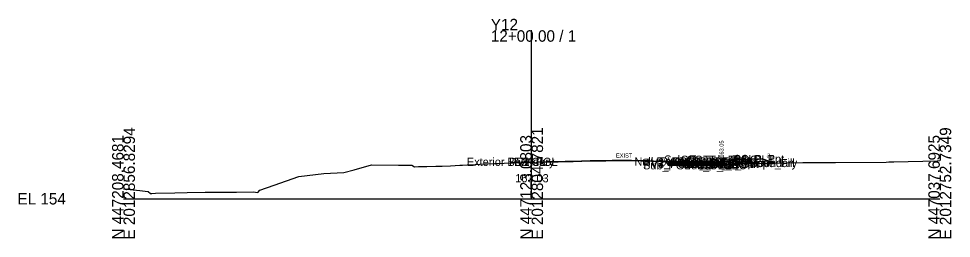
# Model space of a CAD drawing. Extents: x -26 to 1203, y -10 to 9542.
# Drawn here: x -25.7 to 202.8, y 3990.3 to 4044.1 of the extents above; entities that cross this region are included whole.
import ezdxf

# ---------------------------------------------------------------- set-up
doc = ezdxf.new("R2010")
doc.units = 0
for name, color, linetype in [('Default', 7, 'Continuous'), ('Exist Cross Section Cell', 7, 'Continuous'), ('Exist XS Center Line Elevation Label', 7, 'Continuous'), ('Exist XS Ground Line', 7, 'Continuous'), ('Prop CMT Conc Surface', 7, 'Continuous'), ('Prop CMT Concrete Structures', 7, 'Continuous'), ('Prop CMT Pvmt Course 1', 7, 'Continuous'), ('Prop CMT Pvmt Course 1 CG', 7, 'Continuous'), ('Prop CMT Pvmt Course 2', 7, 'Continuous'), ('Prop CMT Pvmt Course 3', 7, 'Continuous'), ('Prop CMT Pvmt Surface', 7, 'Continuous'), ('Prop CMT Slope Grass', 7, 'Continuous'), ('Prop CMT Subgrade Earthwork', 7, 'Continuous'), ('Prop XS Earthwork Shape', 7, 'Continuous'), ('Prop XS Hydro Elevations', 7, 'Continuous'), ('Prop XS SE Text', 7, 'Continuous'), ('Prop XS Side Slope Text', 7, 'Continuous'), ('Scratch_Level_0', 7, 'Continuous')]:
    doc.layers.add(name, color=color, linetype=linetype)

msp = doc.modelspace()

# ---------------------------------------------------------------- linework, layer by layer
at = {"layer": 'Exist Cross Section Cell'}
for p, q in [((100, 4000), (100, 4041.25)), ((0, 4000), (100, 4000)), ((100, 4000), (200, 4000))]:
    msp.add_line(p, q, dxfattribs=at)
at = {"layer": 'Exist XS Ground Line'}
msp.add_lwpolyline([(0, 4002.46), (3.98, 4002), (5.32, 4001.82), (6.04, 4001.75), (6.62, 4001.26), (6.95, 4001.29), (7.8, 4001.38), (12.55, 4001.47), (15.61, 4001.54), (20.02, 4001.61), (27.65, 4001.63), (31.86, 4001.66), (32.36, 4001.62), (32.92, 4001.57), (33.44, 4002.07), (36.88, 4003.29), (42.93, 4005.45), (49.12, 4006.16), (53.97, 4006.45), (56.51, 4007.1), (60.78, 4008.34), (67.35, 4008.23), (70.65, 4008.25), (71.32, 4007.83), (72.27, 4007.86), (73.24, 4007.89), (73.76, 4007.91), (74.31, 4007.9), (76.51, 4007.94), (77.13, 4007.94), (77.71, 4007.95), (78.07, 4007.95), (80.13, 4008.06), (81.29, 4008.13), (82.38, 4008.19), (83.05, 4008.23), (84.22, 4008.29), (86.13, 4008.39), (88.42, 4008.51), (89.05, 4008.53), (90.88, 4008.61), (91.46, 4008.64), (91.81, 4008.65), (93.26, 4008.71), (94.73, 4008.77), (95.66, 4008.82), (97.58, 4008.91), (98.36, 4008.94), (98.9, 4008.71), (99.5, 4009.01), (100, 4009.03), (100.4, 4009.04), (101, 4008.74), (101.38, 4008.98), (103.54, 4009.01), (104.22, 4009.02), (105.33, 4009.05), (106.04, 4009.06), (106.47, 4009.07), (108.25, 4009.11), (109.4, 4009.13), (110.14, 4009.15), (112.34, 4009.2), (114.35, 4009.25), (114.93, 4009.26), (115.25, 4009.27), (115.74, 4009.27), (118.16, 4009.31), (119.71, 4009.34), (121.08, 4009.36), (121.56, 4009.36), (123.21, 4009.36), (124.01, 4009.35), (124.51, 4009.34), (126.94, 4009.29), (127.84, 4009.27), (129.33, 4009.22), (129.89, 4009.2), (131.49, 4009.16), (132.8, 4009.12), (133.49, 4009.1), (135.27, 4009.04), (135.66, 4009.09), (137.45, 4008.92), (141.7, 4008.69), (142.97, 4008.63), (145.36, 4008.52), (147.63, 4008.57), (149.64, 4008.58), (158.4, 4008.74), (166.49, 4008.84), (174.42, 4008.87), (186.85, 4008.99), (187.51, 4009), (188.73, 4009.01), (199.36, 4009.32), (200, 4009.37)], dxfattribs=at)
at = {"layer": 'Prop CMT Conc Surface'}
msp.add_lwpolyline([(144.52, 4009.13), (146.52, 4009.05), (146.52, 4009.55), (147.02, 4009.55)], dxfattribs=at)
at = {"layer": 'Prop CMT Concrete Structures'}
for points in [[(144.52, 4009.13), (146.52, 4009.05), (146.52, 4009.55), (147.02, 4009.55)], [(147.02, 4009.55), (147.02, 4008.55), (144.52, 4008.55)], [(144.52, 4008.55), (144.52, 4009.13)]]:
    msp.add_lwpolyline(points, dxfattribs=at)
at = {"layer": 'Prop CMT Pvmt Course 1'}
for points in [[(133.49, 4009.1), (133.46, 4009.11), (133.28, 4009.11), (132.8, 4009.12), (131.49, 4009.16), (129.89, 4009.2), (129.68, 4009.21), (129.33, 4009.22), (127.84, 4009.27), (126.94, 4009.29), (124.51, 4009.34), (124.01, 4009.35), (123.21, 4009.36), (121.56, 4009.36), (121.08, 4009.36), (119.71, 4009.34), (118.16, 4009.31), (115.74, 4009.27), (115.25, 4009.27), (114.93, 4009.26), (114.35, 4009.25), (112.54, 4009.21), (112.34, 4009.2), (112.18, 4009.2), (110.14, 4009.15), (109.4, 4009.13), (108.25, 4009.11), (106.47, 4009.07), (106.04, 4009.06), (105.33, 4009.05), (104.22, 4009.02), (103.54, 4009.01), (101.38, 4008.98), (101.29, 4008.98), (101.29, 4008.98), (101.28, 4008.98), (101, 4008.74), (100.49, 4009), (100.4, 4009.04), (100, 4009.03)], [(100, 4009.03), (100, 4009.03)], [(133.49, 4009.1), (144.52, 4009.13)], [(133.49, 4009.1), (133.49, 4009.1)], [(133.49, 4008.85), (133.49, 4009.1)], [(144.52, 4008.88), (133.49, 4008.85)], [(144.52, 4009.13), (144.52, 4008.88)]]:
    msp.add_lwpolyline(points, dxfattribs=at)
at = {"layer": 'Prop CMT Pvmt Course 1 CG'}
for points in [[(144.52, 4008.55), (147.52, 4008.55), (147.86, 4008.22)], [(144.52, 4008.21), (144.52, 4008.55)], [(147.86, 4008.22), (144.52, 4008.21)]]:
    msp.add_lwpolyline(points, dxfattribs=at)
at = {"layer": 'Prop CMT Pvmt Course 2'}
for points in [[(133.49, 4008.85), (144.52, 4008.88)], [(133.49, 4008.52), (133.49, 4008.85)], [(144.52, 4008.55), (133.49, 4008.52)], [(144.52, 4008.88), (144.52, 4008.55)]]:
    msp.add_lwpolyline(points, dxfattribs=at)
at = {"layer": 'Prop CMT Pvmt Course 3'}
for points in [[(133.49, 4008.52), (144.52, 4008.55)], [(133.49, 4008.19), (133.49, 4008.52)], [(144.52, 4008.55), (144.52, 4008.21)], [(144.52, 4008.21), (133.49, 4008.19)]]:
    msp.add_lwpolyline(points, dxfattribs=at)
at = {"layer": 'Prop CMT Pvmt Surface'}
msp.add_lwpolyline([(133.49, 4009.1), (144.52, 4009.13)], dxfattribs=at)
at = {"layer": 'Prop CMT Slope Grass'}
msp.add_lwpolyline([(147.02, 4009.55), (156.52, 4009.74), (159.51, 4008.75)], dxfattribs=at)
at = {"layer": 'Prop CMT Subgrade Earthwork'}
for points in [[(133.49, 4008.19), (133.49, 4009.1)], [(144.52, 4008.21), (147.86, 4008.22), (149.23, 4009.6)], [(133.49, 4008.19), (144.52, 4008.21)], [(144.52, 4008.21), (133.49, 4008.19)]]:
    msp.add_lwpolyline(points, dxfattribs=at)
at = {"layer": 'Prop XS Earthwork Shape'}
for points in [[(135.27, 4009.04), (135.66, 4009.09), (137.45, 4008.92), (141.7, 4008.69), (142.97, 4008.63), (144.52, 4008.55), (144.73, 4008.55), (145.36, 4008.52), (147.02, 4008.55), (147.63, 4008.57), (148.21, 4008.57), (147.86, 4008.22), (144.52, 4008.21), (133.49, 4008.19), (133.49, 4009.1)], [(158.4, 4008.74), (159.51, 4008.75), (156.52, 4009.74), (149.23, 4009.6), (148.21, 4008.57), (149.64, 4008.58)]]:
    msp.add_lwpolyline(points, close=True, dxfattribs=at)

# ---------------------------------------------------------------- texts
at = {"layer": 'Default'}
msp.add_text('-', height=0.0001, dxfattribs=at).set_placement((0, 4000))
at = {"layer": 'Exist Cross Section Cell'}
for s, p in [('Y12', (90, 4041.25)), ('12+00.00 / 1', (90, 4038.45)), ('EL 154', (-26, 3998.6))]:
    msp.add_text(s, height=2.8, dxfattribs=at).set_placement(p)
for s, p in [('N 447208.4681', (0, 3990)), ('E 2012856.8294', (2.8, 3990)), ('N 447123.0803', (100, 3990)), ('E 2012804.7821', (102.8, 3990)), ('N 447037.6925', (200, 3990)), ('E 2012752.7349', (202.8, 3990))]:
    msp.add_text(s, height=2.8, rotation=90, dxfattribs=at).set_placement(p)
at = {"layer": 'Exist XS Center Line Elevation Label'}
msp.add_text('163.03', height=2, dxfattribs=at).set_placement((95.99, 4004.03))
at = {"layer": 'Prop XS Hydro Elevations'}
msp.add_text('163.05', height=1, rotation=90, dxfattribs=at).set_placement((147.02, 4010.05))
at = {"layer": 'Prop XS SE Text'}
msp.add_text('EXIST', height=1, rotation=0.1311, dxfattribs=at).set_placement((120.67, 4010.08))
at = {"layer": 'Prop XS Side Slope Text'}
msp.add_text('3:1', height=1, rotation=341.5651, dxfattribs=at).set_placement((157.5, 4010.21))
at = {"layer": 'Scratch_Level_0'}
for s, p in [('CSLP_Pnt', (149.39, 4008.74)), ('Exterior Boundary', (84.14, 4008.03)), ('PV1_PGL', (94.47, 4008.03)), ('EX CL', (95.67, 4008.03)), ('Null Ex EOP', (125.19, 4008.1)), ('Sub_PGL', (127.31, 4007.19)), ('PV2_PGL', (127.4, 4007.85)), ('PV3_PGL', (127.4, 4007.52)), ('PV1', (131.57, 4008.1)), ('Sub_Trench_Out_DLT', (132.49, 4008.6)), ('CG_Top_Face', (136.48, 4008.55)), ('CG1_Shelf_Out', (136.77, 4007.55)), ('CG_Bot_IE', (137.13, 4007.55)), ('Sub_OEOT', (137.29, 4007.21)), ('CG_Top_Gut', (137.45, 4008.05)), ('PV2_OEOT', (137.39, 4007.88)), ('PV3_OEOT', (137.39, 4007.55)), ('CG_Top_BOC', (138, 4008.55)), ('CG_Bot_BOC', (138.03, 4007.55)), ('PV1_OEOT', (137.96, 4008.13)), ('Sub_OEOP', (140.66, 4007.22)), ('Exterior Boundary', (143.65, 4007.75)), ('Slope_Fill', (152.72, 4007.75))]:
    msp.add_text(s, height=2, dxfattribs=at).set_placement(p)

doc.saveas('drawing.dxf')
